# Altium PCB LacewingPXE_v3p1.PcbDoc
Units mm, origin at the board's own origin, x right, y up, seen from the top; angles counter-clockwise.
Board outline 62.74 x 108.59 mm, 2 copper layers (Top Layer, Bottom Layer); 94 components, 74 nets, 455 pads, 79 vias.
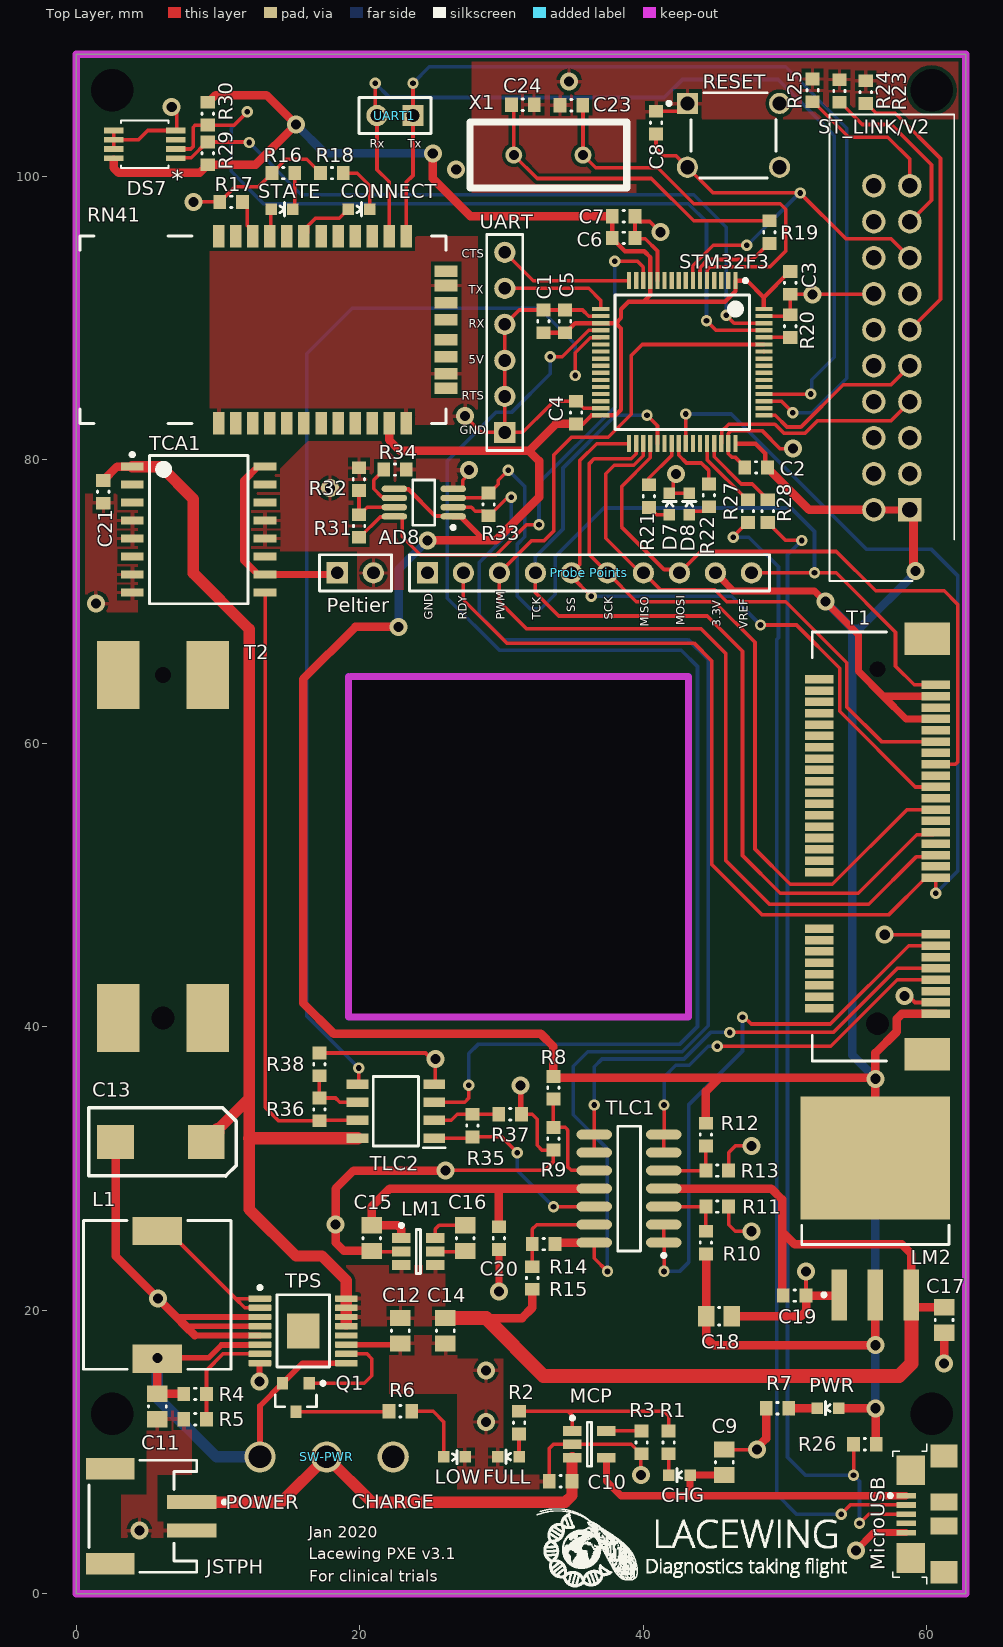
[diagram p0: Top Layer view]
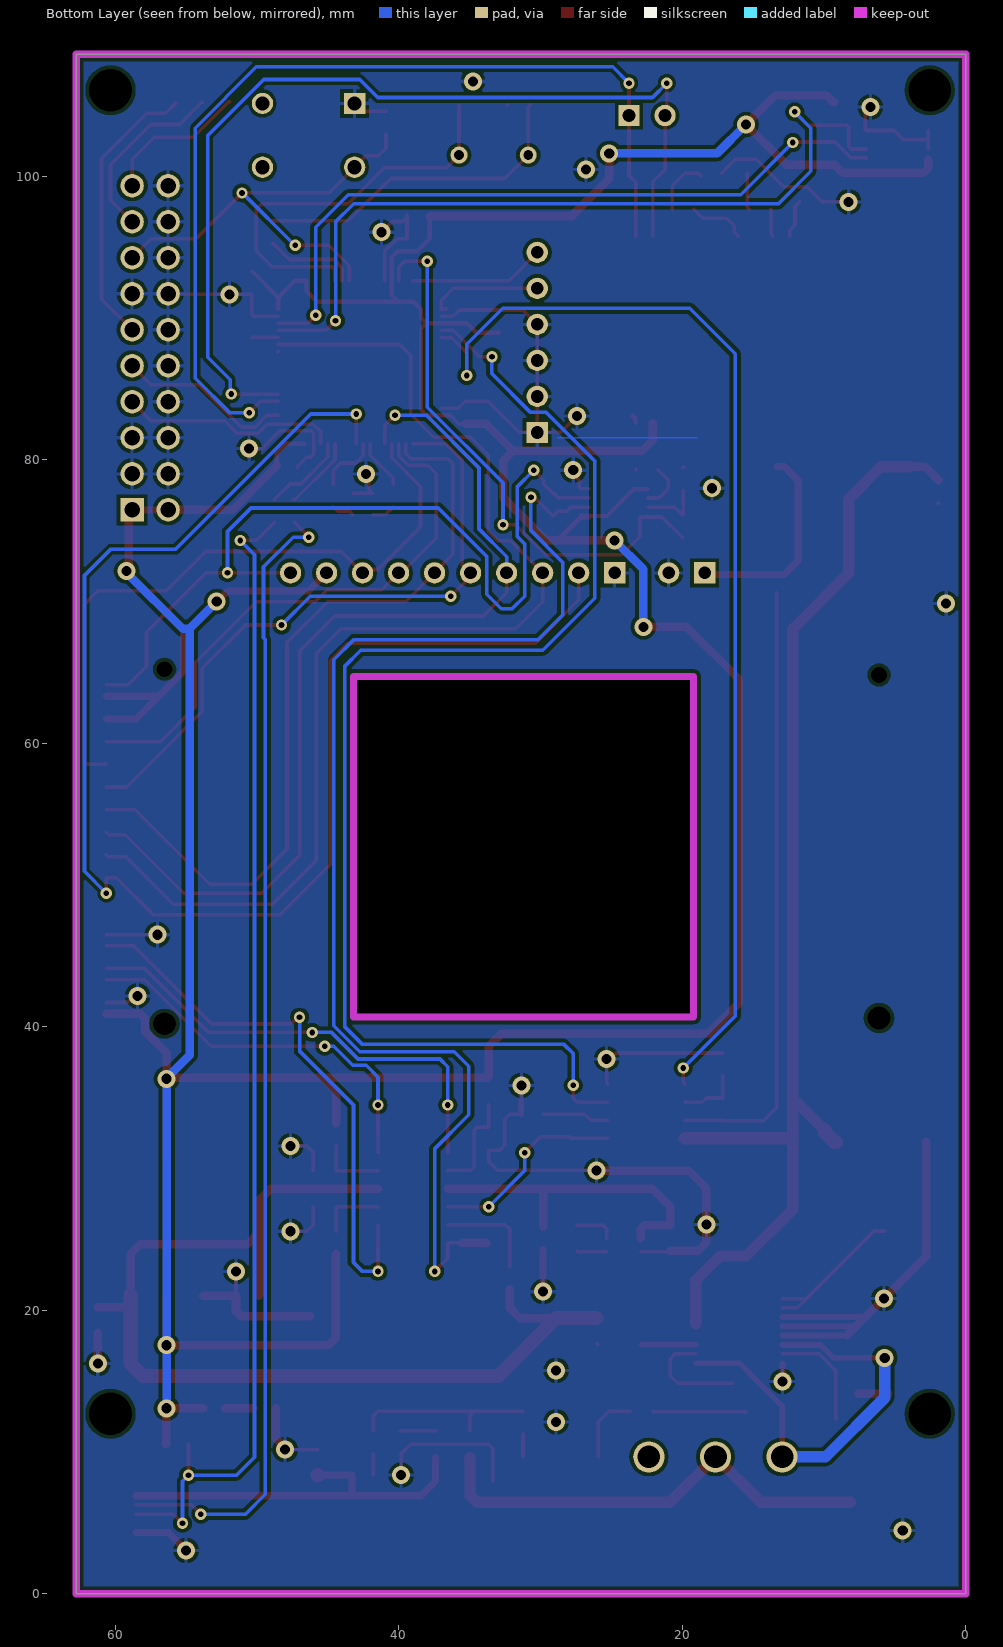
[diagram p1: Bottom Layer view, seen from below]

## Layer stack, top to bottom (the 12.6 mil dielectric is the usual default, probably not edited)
Top Solder: solder mask 0.0102, Solder Resist, Dk 3.5
Top Layer: signal copper 0.0356
Dielectric 1: dielectric 0.32, FR-4, Dk 4.8
Bottom Layer: signal copper 0.0356
Bottom Solder: solder mask 0.0102, Solder Resist, Dk 3.5

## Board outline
0,0 62.738,0 62.738,108.585 0,108.585
cut-out: 43.188,40.672 19.188,40.672 19.188,64.705 43.188,64.705

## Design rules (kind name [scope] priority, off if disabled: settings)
Clearance [All] p1: gap=0.254 ignorepadtopadclearanceinfootprint=TRUE except(0: Arc-Hole Track-Hole SMDPad-Hole THPad-Hole Via-Hole Fill-Hole Poly-Hole Region-Hole Text-Hole; 0.2: Arc-Arc Arc-Track Arc-SMDPad Track-Track Track-SMDPad)
ComponentClearance [All] p1 off: gap=0.254 collisioncheckmode=3 verticalgap=0.254 showdistances=FALSE
HoleSize [All] p1: absolutevalues=TRUE maxlimit=3 minlimit=0.025 maxpercent=80.000 minpercent=20.000
MinimumSolderMaskSliver [All] p1: minsoldermaskwidth=0.1
PolygonConnect [All] p1: connectstyle=Relief reliefconductorwidth=0.254 reliefentries=4 polygonreliefangle="90 Angle" airgapwidth=0.254
RoutingVias [All] p1: holewidth=0.711 width=1.27 viastyle="Through Hole" minholewidth=0.4 minwidth=0.8 maxholewidth=0.711 maxwidth=1.27
SilkToSilkClearance [All] p1: silktosilkclearance=0.1
SilkToSolderMaskClearance [IsPad] p1: minsilkscreentomaskgap=0.1 clearancetoexposedcopper=TRUE
SolderMaskExpansion [All] p1: expansion=0.102 istentingtop=FALSE
Width Width_+5VDD [InNet('+5VDD')] p1: maxlimit=1 minlimit=0.4 preferedwidth=1 minimp=50.000000 maximp=50.000000 favimp=50.000000
Width Width_-5VDD [InNet('-5VDD')] p2: maxlimit=1 minlimit=0.5 preferedwidth=1 minimp=50.000000 maximp=50.000000 favimp=50.000000
Width Width_VLi [InNet('VLiPo')] p3: maxlimit=1 minlimit=0.5 preferedwidth=1 minimp=50.000000 maximp=50.000000 favimp=50.000000
Width Width_VPelt [InNet('Vpeltier')] p4: maxlimit=1 minlimit=0.5 preferedwidth=1 minimp=50.000000 maximp=50.000000 favimp=50.000000
Width Width_5VUSB [InNet('5VUSB')] p5: maxlimit=1 minlimit=0.5 preferedwidth=1 minimp=50.000000 maximp=50.000000 favimp=50.000000
Width Width_VBat [InNet('VBAT')] p6: maxlimit=1 minlimit=0.4 preferedwidth=1 minimp=50.000000 maximp=50.000000 favimp=50.000000
Width Width_3VDD [InNet('3.3VDD')] p7: maxlimit=0.6 minlimit=0.254 preferedwidth=0.6 minimp=50.000000 maximp=50.000000 favimp=50.000000
Width [All] p8: maxlimit=0.6 minlimit=0.254 preferedwidth=0.254 minimp=50.000000 maximp=50.000000 favimp=50.000000
25 further rules are at their usual default settings.

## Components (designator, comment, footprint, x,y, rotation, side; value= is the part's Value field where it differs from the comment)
AD8 "AD8237" ADI-RM-8_N 24.511,76.962 r180 top (schematic designator U3)
C1 "4.7uF" CAPC0603(1608)100_N 32.948,89.751 r90 top
C2 "100nF" CAPC0603(1608)100_N 47.95,79.442 r180 top
C3 "100nF" CAPC0603(1608)100_N 50.363,92.456 r270 top
C4 "100nF" CAPC0603(1608)100_N 35.25,83.312 r90 top
C5 "100nF" CAPC0603(1608)100_N 34.472,89.751 r90 top
C6 "1uF" CAPC0603(1608)100_N 38.608,95.631 r0 top
C7 "10nF" CAPC0603(1608)100_N 38.608,97.163 r0 top
C8 "100nF" CAPC0603(1608)100_N 40.894,103.759 r90 top
C9 "10µF" CAPC0805(2012)75_N 45.72,9.271 r270 top
C10 "4.7µF" CAPC0603(1608)100_N 34.163,7.928 r0 top
C11 "10µF" CAPC0805(2012)75_N 5.715,13.208 r90 top
C12 "2.2µF" CAPC0805(2012)75_N 22.86,18.542 r90 top
C13 "220µF" AVX-CAPC7343_V 5.969,31.877 r180 top
C14 "2.2µF" CAPC0805(2012)75_N 26.035,18.542 r90 top
C15 "10µF" CAPC0805(2012)75_N 20.844,25.08 r270 top
C16 "10µF" CAPC0805(2012)75_N 27.432,25.08 r90 top
C17 "10µF" CAPC0805(2012)75_N 61.214,19.304 r270 top
C18 "10µF" CAPC0805(2012)75_N 45.339,19.569 r180 top
C19 "0.1µF" CAPC0603(1608)100_N 50.673,21.023 r180 top
C20 "0.1µF" CAPC0603(1608)100_N 29.807,25.08 r90 top
C21 "0.1µF" CAPC0603(1608)100_N 1.905,77.724 r90 top
C23 "18pF" CAPC0603(1608)100_N 34.925,104.991 r180 top
C24 "18pF" CAPC0603(1608)100_N 31.496,105.029 r0 top
CHG "Yellow" LED-0603 42.545,8.36 r90 top (schematic designator D1)
CONNECT "Green" LED-0603 19.939,97.663 r270 top (schematic designator D5)
D7 "Red" LED-0603 41.835,76.857 r0 top
D8 "Green" LED-0603 43.229,76.857 r0 top
DS7 "DS7505U+" 21-0036K 4.826,102.235 r180 top value=Value (schematic designator U2)
FULL "Green" LED-0603 30.48,9.652 r90 top (schematic designator D2)
JSTPH "Li-Poly battery" "JST- S2B-PH-SM4-TB(LF)(SN)-2_V" 4.699,5.461 r270 top
L1 "15µH" "WE-PD 1050" 5.715,21.082 r90 top
LM1 "LM2776 Switched-capacitor inverter" TI-DBV6_M 24.13,24.13 r0 top
LM2 "LM1086IS-3.3, 3.3V voltage regulator" TS3B_M 56.368,27.184 r90 top
LOW "Red" LED-0603 26.67,9.652 r270 top (schematic designator D3)
MCP "MCP73831T-2ACI/OT Li-Poly battery charger" SOT-23-OT5_M 36.195,10.541 r0 top
MicroUSB "ZX62R-B-5P" HIRO-ZX62R-B-5P_V 59.876,5.611 r90 top (schematic designator MicroUSB-TypeB)
Peltier "Header 2" HDR1X2 18.415,72.009 r0 top
"Probe Points" "Header 10" HDR1X10 24.765,72.009 r0 top
PWR "Blue" LED-0603 53.017,13.081 r90 top (schematic designator D4)
Q1 "MMUN2133LT1G" ONSC-SOT-23-3-318-08_V 15.494,13.843 r270 top
R1 "1k" RESC0603(1608)_N 41.783,10.668 r90 top
R2 "1k" RESC0603(1608)_N 31.23,12.065 r90 top
R3 "2k" RESC0603(1608)_N 39.878,10.668 r270 top
R4 "2.7M" RESC0603(1608)_N 8.382,14.097 r180 top
R5 "470k" RESC0603(1608)_N 8.382,12.308 r180 top
R6 "1k5" RESC0603(1608)_N 22.86,12.865 r180 top
R7 "200" RESC0603(1608)_N 49.461,13.081 r180 top
R8 "75k" RESC0603(1608)_N 33.655,35.687 r270 top
R9 "24k" RESC0603(1608)_N 33.655,32.093 r270 top
R10 "51k" RESC0603(1608)_N 44.412,24.765 r90 top
R11 "30k" RESC0603(1608)_N 45.212,27.305 r0 top
R12 "51k" RESC0603(1608)_N 44.412,32.385 r270 top
R13 "51k" RESC0603(1608)_N 45.212,29.845 r0 top
R14 "20k" RESC0603(1608)_N 32.965,24.659 r180 top
R15 "20k" RESC0603(1608)_N 32.165,22.269 r270 top
R16 "470" RESC0603(1608)_N 14.605,100.203 r0 top
R17 "10k" RESC0603(1608)_N 10.922,98.171 r0 top
R18 "470" RESC0603(1608)_N 18.034,100.203 r0 top
R19 "0" RESC0603(1608)_N 48.895,96.035 r270 top
R20 "10k" RESC0603(1608)_N 50.363,89.408 r90 top
R21 "510" RESC0603(1608)_N 40.386,77.414 r90 top
R22 "510" RESC0603(1608)_N 44.623,77.474 r90 top
R23 "10k" RESC0603(1608)_N 55.686,105.918 r270 top
R24 "10k" RESC0603(1608)_N 53.828,105.997 r270 top
R25 "10k" RESC0603(1608)_N 51.931,106.046 r270 top
R26 "1.5k" RESC0603(1608)_N 55.626,10.541 r0 top
R27 "22" RESC0603(1608)_N 47.371,76.365 r90 top
R28 "22" RESC0603(1608)_N 48.768,76.365 r90 top
R29 "10k" RESC0603(1608)_N 9.271,101.6 r270 top
R30 "10k" RESC0603(1608)_N 9.271,104.394 r90 top
R31 "1M" RESC0603(1608)_N 19.95,75.311 r270 top
R32 "1k" RESC0603(1608)_N 19.939,78.613 r270 top
R33 "10k" RESC0603(1608)_N 29.083,76.835 r270 top
R34 "1k" RESC0603(1608)_N 22.479,79.294 r180 top
R35 "10k" RESC0603(1608)_N 27.94,33.02 r270 top
R36 "10k" RESC0603(1608)_N 17.145,34.163 r270 top
R37 "20k" RESC0603(1608)_N 30.607,33.82 r180 top
R38 "20k" RESC0603(1608)_N 17.145,37.338 r270 top
RESET "Tactile switch" OMRON-B3F-1000-4_V 46.355,102.87 r0 top (schematic designator SW-RST1)
RN41 "Bluetooth module w/ antenna" RN41 18.071,89.154 r0 top (schematic designator RN)
ST_LINK/V2 "JTAG Programmer" JTAG2 58.801,76.454 r90 top (schematic designator CN1)
STATE "Red" LED-0603 14.517,97.663 r270 top (schematic designator D6)
STM32F3 "STM32F303RET6" STM-LQFP64_V 42.743,86.868 r270 top (schematic designator U1)
SW-PWR "SW-SPDT" "SWITCH SPDT CS12ANW03" 17.653,9.652 r90 top
T1 "Mini PCIe connector" "Molex Conn-67910" 56.515,52.705 r90 top
T2 "Mini PCIe Latch" "Molex Latch-48099" 6.115,52.705 r90 top
TCA1 "TCA0372 Dual high power Op-amp" ONSC-SOIC-16-751G-03_V 8.636,75.057 r0 top
TLC1 "TLC2274 Quad Op-amp" TI-D14_M 38.989,28.575 r180 top
TLC2 "TLC2272AID" SOIC127P600X175-8N 22.543,34.036 r180 top
TPS "TPS61032 Boost SMPS controller" PW0016A_M 16.002,18.542 r0 top
UART "Header 6" HDR1X6 30.226,81.915 r90 top (schematic designator UART2)
UART1 "Header 2" HDR1X2 23.749,104.267 r180 top
X1 "8MHz" QCL 33.301,101.473 r180 top

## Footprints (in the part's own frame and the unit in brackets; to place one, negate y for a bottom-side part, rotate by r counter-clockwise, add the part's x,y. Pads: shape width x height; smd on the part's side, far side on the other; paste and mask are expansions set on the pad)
21-0036K [mil]
  rect 54x16 smd paste+0 mask+0: 1(-86,38.39) 2(-86,12.8) 3(-86,-12.8) 4(-86,-38.39) 5(86,-38.39) 6(86,-12.8) 7(86,12.8) 8(86,38.39)
  silkscreen extent -66,-66 66,66, body extent 0,0 10,10, height 10
ADI-RM-8_N [mm] "SOP, 8-Leads, Body 3x3mm, Pitch 0.65mm, IPC Medium Density"
  oval 1.8x0.45 smd: 1(-2.075,0.975) 2(-2.075,0.325) 3(-2.075,-0.325) 4(-2.075,-0.975) 5(2.075,-0.975) 6(2.075,-0.325) 7(2.075,0.325) 8(2.075,0.975)
  silkscreen extent -2.2,-1.6 0.77,1.87, body extent -1.6,-1.6 1.6,1.6, height 1.1
AVX-CAPC7343_V [mm] "SMT Capacitor, 2 Leads, Body 7.3x4.3mm"
  rect 2.6x2.4 smd: 1(-3.202,0.007) 2(3.198,0.007)
  silkscreen extent -5.33,-2.39 5.08,2.41, body extent -3.49,-2.03 3.51,2.04, height 4.05
CAPC0603(1608)100_N [mm] "Chip Capacitor, Body 1.6x0.8mm, Height 1.0mm, IPC Medium Density"
  rect 0.9x1 smd: 1(-0.8,0) 2(0.8,0)
  silkscreen extent -0.05,-0.4 0.05,0.4, body extent -0.87,-0.48 0.88,0.47, height 1
CAPC0805(2012)75_N [mm] "Chip Capacitor, Body 2.0x1.2mm, Height 0.75mm, IPC Medium Density"
  rect 1.15x1.45 smd: 1(-0.9,0) 2(0.9,0)
  silkscreen extent -0.05,-0.62 0.05,0.63, body extent -1.1,-0.72 1.1,0.73, height 0.75
HDR1X2 [mm] "Connector; Header; 2 Position"
  rect 1.5x1.5 hole 0.9: 1(0,0)
  round 1.5 hole 0.9: 2(2.54,0)
  silkscreen extent -1.27,-1.27 3.81,1.27
HDR1X6 [mm] "Connector; Header; 6 Position"
  rect 1.5x1.5 hole 0.9: 1(0,0)
  round 1.5 hole 0.9: 2(2.54,0) 3(5.08,0) 4(7.62,0) 5(10.16,0) 6(12.7,0)
  silkscreen extent -1.27,-1.27 13.97,1.27
HDR1X10 [mm] "Connector; Header; 10 Position"
  rect 1.5x1.5 hole 0.9: 1(0,0)
  round 1.5 hole 0.9: 2(2.54,0) 3(5.08,0) 4(7.62,0) 5(10.16,0) 6(12.7,0) 7(15.24,0) 8(17.78,0) 9(20.32,0) 10(22.86,0)
  silkscreen extent -1.27,-1.27 24.13,1.27
HIRO-ZX62R-B-5P_V [mm] "USB Micro-B R/A Connector"
  rect 0.4x1.35 smd: 1(1.3,1.338) 2(0.65,1.338) 3(0,1.338) 4(-0.65,1.338) 5(-1.3,1.338)
  rect 2.1x2 smd: 6(-3.1,1.012) 11(3.1,1.012)
  rect 1.6x1.9 smd: 7(-4.1,-1.338) 10(4.1,-1.338)
  rect 1.2x1.9 smd: 8(-0.85,-1.338) 9(0.85,-1.338)
  silkscreen extent -4.95,-0.13 4.95,2.58, body extent -4.4,-3.95 4.4,1.78, height 2.71
"JST- S2B-PH-SM4-TB(LF)(SN)-2_V" [mm] "SMD, 2-Leads, Body 7.9x7.6mm, Pitch 2mm"
  rect 1x3.5 smd: 1(-1,3.45) 2(1,3.45)
  rect 1.5x3.4 smd: MP1(-3.35,-2.3) MP2(3.35,-2.3)
  silkscreen extent -3.95,-3.8 3.95,5.88, body extent -3.95,-3.8 3.95,4.8, height 5.6
JTAG2 [mm] "Header, Vertical Shrouded, 100 mil pitch; 25 mil lead width, 20 pins, 2 rows, 10 pins per row, 1295 mil L X 346 mil W X 346 mil H body"
  rect 1.652x1.652 hole 1.101 paste-1.652: 1(0,0)
  round 1.652 hole 1.101 paste-1.652: 2(0,2.54) 3(2.54,0) 4(2.54,2.54) 5(5.08,0) 6(5.08,2.54) 7(7.62,0) 8(7.62,2.54) 9(10.16,0) 10(10.16,2.54) 11(12.7,0) 12(12.7,2.54) 13(15.24,0) 14(15.24,2.54) 15(17.78,0) 16(17.78,2.54) 17(20.32,0) 18(20.32,2.54) 19(22.86,0) 20(22.86,2.54)
  silkscreen extent -5.02,-3.12 27.88,5.66, body extent -3.18,-3.56 26.04,5.92, height 8.89
LED-0603 [mil] "LED-0603"
  rect 32x32 smd: A(0,-29.53) C(0,30)
  silkscreen extent -18,-6 19,7
"Molex Conn-67910" [mm] "Board-to-Board Connector, SMT, Right Angle, Pitch 0.8mm, 52-Position, Female"
  rect 0.6x2 smd: 1(-11.8,-4.1) 2(-11.4,4.1) 3(-11,-4.1) 4(-10.6,4.1) 5(-10.2,-4.1) 6(-9.8,4.1) 7(-9.4,-4.1) 8(-9,4.1) 9(-8.6,-4.1) 10(-8.2,4.1) 11(-7.8,-4.1) 12(-7.4,4.1) 13(-7,-4.1) 14(-6.6,4.1) 15(-6.2,-4.1) 16(-5.8,4.1) 17(-2.2,-4.1) 18(-1.8,4.1) 19(-1.4,-4.1) 20(-1,4.1) 21(-0.6,-4.1) 22(-0.2,4.1) 23(0.2,-4.1) 24(0.6,4.1) 25(1,-4.1) 26(1.4,4.1) 27(1.8,-4.1) 28(2.2,4.1) 29(2.6,-4.1) 30(3,4.1) 31(3.4,-4.1) 32(3.8,4.1) 33(4.2,-4.1) 34(4.6,4.1) 35(5,-4.1) 36(5.4,4.1) 37(5.8,-4.1) 38(6.2,4.1) 39(6.6,-4.1) 40(7,4.1) 41(7.4,-4.1) 42(7.8,4.1) 43(8.2,-4.1) 44(8.6,4.1) 45(9,-4.1) 46(9.4,4.1) 47(9.8,-4.1) 48(10.2,4.1) 49(10.6,-4.1) 50(11,4.1) 51(11.4,-4.1) 52(11.8,4.1)
  round 1.3 hole 1.6 unplated: MH1(-12.5,0)
  round 0.8 hole 1.1 unplated: MH2(12.5,0)
  rect 2.3x3.2 smd: MP1C(-14.65,-3.5) MP2C(14.65,-3.5)
  silkscreen extent -15.12,-0.64 15.12,4.6, body extent -15,-5 15,4.5, height 5.6
"Molex Latch-48099" [mm]
  round 1.3 hole 1.6 unplated: MH3(-12.1,0)
  round 0.8 hole 1.1 unplated: MH4(12.1,0)
  rect 4.8x3 smd: MP1L(-12.1,3.15) MP2L(-12.1,-3.15) MP3L(12.1,3.15) MP4L(12.1,-3.15)
OMRON-B3F-1000-4_V [mm] "TH, 4-Leads, Body 6x6mm"
  rect 1.5x1.5 hole 1 paste+0: 1(-3.25,2.25)
  round 1.5 hole 1 paste+0: 2(3.25,2.25) 3(-3.25,-2.25) 4(3.25,-2.25)
  silkscreen extent -4.67,-3 3,3, body extent -3,-3 3,3, height 4.5
ONSC-SOIC-16-751G-03_V [mm] "SOIC, 16-Leads, Body 10.45x7.6mm, Pitch 1.27mm"
  rect 1.62x0.58 smd: 1(-4.69,4.445) 2(-4.69,3.175) 3(-4.69,1.905) 4(-4.69,0.635) 5(-4.69,-0.635) 6(-4.69,-1.905) 7(-4.69,-3.175) 8(-4.69,-4.445) 9(4.69,-4.445) 10(4.69,-3.175) 11(4.69,-1.905) 12(4.69,-0.635) 13(4.69,0.635) 14(4.69,1.905) 15(4.69,3.175) 16(4.69,4.445)
  silkscreen extent -4.81,-5.23 3.48,5.41, body extent -3.8,-5.23 3.8,5.23, height 2.65
ONSC-SOT-23-3-318-08_V [mm] "SOT23, 3-Leads, Body 2.92x1.3mm, Pitch 0.95mm"
  rect 0.9x0.8 smd: 1(-1,0.95) 2(-1,-0.95) 3(1,0)
  silkscreen extent -1.12,-1.46 0.65,2.03, body extent -0.65,-1.46 0.65,1.46, height 1.11
PW0016A_M [mm] "SOP, 16-Leads, Body 5.1x4.5mm, Pitch 0.65mm, IPC Low Density"
  rrect22% 1.6x0.45 smd: 1(-3.05,2.275) 2(-3.05,1.625) 3(-3.05,0.975) 4(-3.05,0.325) 5(-3.05,-0.325) 6(-3.05,-0.975) 7(-3.05,-1.625) 8(-3.05,-2.275) 9(3.05,-2.275) 10(3.05,-1.625) 11(3.05,-0.975) 12(3.05,-0.325) 13(3.05,0.325) 14(3.05,0.975) 15(3.05,1.625) 16(3.05,2.275)
  rect 2.31x2.46 smd: PowerPAD(0,0)
  silkscreen extent -3.17,-2.55 1.85,3.17, body extent -3.21,-2.5 3.21,2.5, height 1
QCL [mm]
  round 1.2 hole 0.7: 1(-2.44,0) 2(2.44,0)
  silkscreen extent -5.53,-2.32 5.53,2.32
RESC0603(1608)_N [mm] "Chip Resistor, Body 1.6x0.8mm, IPC Medium Density"
  rect 0.9x1 smd: 1(-0.8,0) 2(0.8,0)
  silkscreen extent -0.05,-0.4 0.05,0.4, body extent -0.85,-0.47 0.85,0.47, height 0.6
RN41 [mil]
  rect 32x63 smd: 1(-315.42,-259.92) 2(-268.18,-259.92) 3(-220.93,-259.92) 4(-173.69,-259.92) 5(-126.44,-259.92) 6(-79.2,-259.92) 7(-31.58,-259.92) 8(15.42,-259.92) 9(63.42,-259.92) 10(110.42,-259.92) 11(157.42,-259.92) 12(204.42,-259.92) 13(204.42,259.92) 14(157.42,259.92) 15(110.42,259.92) 16(63.42,259.92) 17(15.42,259.92) 18(-31.58,259.92) 19(-79.2,259.92) 20(-126.44,259.92) 21(-173.69,259.92) 22(-220.93,259.92) 23(-268.18,259.92) 24(-315.42,259.92)
  rect 63x32 smd: 28(315.42,122.92) 29(315.42,-122.13) 30(315.42,162.92) 31(315.42,74.92) 32(315.42,27.92) 33(315.42,-27.64) 34(315.42,-74.88) 35(315.42,-162.37)
  silkscreen extent -701,-260 315,260
SOIC127P600X175-8N [mm]
  rect 1.525x0.65 smd: 1(-2.712,1.905) 2(-2.712,0.635) 3(-2.712,-0.635) 4(-2.712,-1.905) 5(2.712,-1.905) 6(2.712,-0.635) 7(2.712,0.635) 8(2.712,1.905)
  silkscreen extent -3.47,-2.45 1.6,2.58, body extent -3,-2.45 3,2.45, height 1.75
SOT-23-OT5_M [mm] "SOT23, 5-Leads, Body 2.9x1.7mm, Pitch 0.95mm, Lead Span 2.8mm, IPC Low Density"
  rect 1.3x0.7 smd: 1(-1.2,0.95) 2(-1.2,0) 3(-1.2,-0.95) 4(1.2,-0.95) 5(1.2,0.95)
  silkscreen extent -1.32,-1.55 0.15,1.97, body extent -0.9,-1.55 0.9,1.55, height 1.45
STM-LQFP64_V [mm] "Thin QFP, 64-Leads, Body 10x10mm, Pitch 0.5mm, ST Recommended"
  rect 1.2x0.3 smd: 1(-5.75,3.75) 2(-5.75,3.25) 3(-5.75,2.75) 4(-5.75,2.25) 5(-5.75,1.75) 6(-5.75,1.25) 7(-5.75,0.75) 8(-5.75,0.25) 9(-5.75,-0.25) 10(-5.75,-0.75) 11(-5.75,-1.25) 12(-5.75,-1.75) 13(-5.75,-2.25) 14(-5.75,-2.75) 15(-5.75,-3.25) 16(-5.75,-3.75) 33(5.75,-3.75) 34(5.75,-3.25) 35(5.75,-2.75) 36(5.75,-2.25) 37(5.75,-1.75) 38(5.75,-1.25) 39(5.75,-0.75) 40(5.75,-0.25) 41(5.75,0.25) 42(5.75,0.75) 43(5.75,1.25) 44(5.75,1.75) 45(5.75,2.25) 46(5.75,2.75) 47(5.75,3.25) 48(5.75,3.75)
  rect 0.3x1.2 smd: 17(-3.75,-5.75) 18(-3.25,-5.75) 19(-2.75,-5.75) 20(-2.25,-5.75) 21(-1.75,-5.75) 22(-1.25,-5.75) 23(-0.75,-5.75) 24(-0.25,-5.75) 25(0.25,-5.75) 26(0.75,-5.75) 27(1.25,-5.75) 28(1.75,-5.75) 29(2.25,-5.75) 30(2.75,-5.75) 31(3.25,-5.75) 32(3.75,-5.75) 49(3.75,5.75) 50(3.25,5.75) 51(2.75,5.75) 52(2.25,5.75) 53(1.75,5.75) 54(1.25,5.75) 55(0.75,5.75) 56(0.25,5.75) 57(-0.25,5.75) 58(-0.75,5.75) 59(-1.25,5.75) 60(-1.75,5.75) 61(-2.25,5.75) 62(-2.75,5.75) 63(-3.25,5.75) 64(-3.75,5.75)
  silkscreen extent -5.87,-4.75 4.75,4.75, body extent -5,-5 5,5, height 1.6
"SWITCH SPDT CS12ANW03" [mm]
  round 2.2 hole 1.6: 1(0,-4.7) 2(0,0) 3(0,4.7)
TI-D14_M [mm] "SOIC, 14-Leads, Body 8.65x3.9mm, Pitch 1.27mm, IPC Low Density"
  oval 2.5x0.7 smd: 1(-2.45,3.81) 2(-2.45,2.54) 3(-2.45,1.27) 4(-2.45,0) 5(-2.45,-1.27) 6(-2.45,-2.54) 7(-2.45,-3.81) 8(2.45,-3.81) 9(2.45,-2.54) 10(2.45,-1.27) 11(2.45,0) 12(2.45,1.27) 13(2.45,2.54) 14(2.45,3.81)
  silkscreen extent -2.58,-4.4 0.8,4.83, body extent -2,-4.38 2,4.38, height 1.75
TI-DBV6_M [mm] "SOT-23, 6-Leads, Body 2.90x1.60mm, Pitch 0.95mm, IPC Low Density"
  rect 1.3x0.7 smd: 1(-1.2,0.95) 2(-1.2,0) 3(-1.2,-0.95) 4(1.2,-0.95) 5(1.2,0) 6(1.2,0.95)
  silkscreen extent -1.32,-1.55 0.15,1.97, body extent -0.87,-1.52 0.87,1.53, height 1.45
TS3B_M [mm] "D2-PAK, 4-Leads, Body 8.6x10.2mm, Pitch 2.54mm, Lead Span 14.2mm, IPC Low Density"
  rect 3.6x1.1 smd: 1(-6.1,2.54) 2(-6.1,0) 3(-6.1,-2.54)
  rect 8.7x10.55 smd: TAB(3.55,0)
  silkscreen extent -6.22,-5.2 -1.2,5.2, body extent -2.55,-5.2 6.34,5.2, height 4.64
"WE-PD 1050" [mm] "SMD Inductor, 2-Leads, Body 10,0x10,0mm"
  rect 2x3.5 smd: 1(-4.5,0) 2(4.5,0)
  silkscreen extent -5.25,-5.2 5.25,5.2, body extent -5,-5 5,5, height 4.75

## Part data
C1 C2 C3 C4 C5 C6 C7 C8 C23 C24: library part CMP-1035-00032-1, "Ceramic CAP0603 (1608 Metric) Thickness 1mm SMD", Case-EIA=0603
C9 C11 C12 C14 C15 C16 C17 C18: library part CMP-1036-00002-1, "Ceramic CAP0805 (2012 Metric) Thickness 0.75mm SMD", Case-EIA=0805, Rated Voltage="10 V"
C10: library part CMP-1035-00032-1, "Ceramic CAP0603 (1608 Metric) Thickness 1mm SMD", Case-EIA=0603, Rated Voltage="10 V"
C13: library part CMP-0279-00002-1, "Capacitor, Tantalum, 220uF 10% 10V MCCT-D (7343-31)", Manufacturer=AVX, PartNumber=TAJD227K010R, Rated Voltage=10V, Tolerance=10%
C19 C20 C21: library part CAP, "Ceramic CAP0603 (1608 Metric) Thickness 1mm SMD", Case-EIA=0603
CHG CONNECT D7 D8 FULL LOW PWR STATE: library part LED0603, "LED SMD 0603"
DS7: library part ds7505u+, "No Description Available"
JSTPH: library part CN-1P-2M-R2, "JST PH 2-pin 2-holder SMD"
L1: library part CMP-1396-00032-1, "SMD-Shielded Power Inductor WE-PD 7447714150, L=15 µH"
LM1: library part LM2776
LM2: library part LM1086IS-3.3
MCP: library part CMP-0133-00143-1, "Miniature Single-Cell, Fully Integrated Li-Ion, Li-Polymer Charge Management Controller, 4.2V, 5-Pin SOT-23, Industrial Temperature, Tape and Reel"
MicroUSB: library part CMP-0031-00001-1, "Connector; USBMicro-B,Reverse type, SMT; 5 Position; Right Angle", Operating Temperature="-30 to 85 degC"
Peltier UART1: "Header, 2-Pin"
"Probe Points": "Header, 10-Pin"
Q1: library part CMP-0630-00284-1, "Digital Transistor (BRT), R1=4.7 kOhm, R2=47 kOhm, PNP Transistor, 3-Pin SOT-23, Pb-Free, Tape and Reel"
R1 R2 R3 R4 R5 R6 R7 R8 R9 R10 R11 R12 R13 R14 R15 R16 R17 R18 R19 R20 R21 R22 R23 R24 R25 R26 R27 R28 R29 R30 R31 R32 R33 R34 R35 R36 R37 R38: library part CMP-1012-00514-1, "RES0603 (1608 Metric)  SMD", Case-EIA=0603
RESET: library part SW-SPST-4_A, "ORMON B3F-10XX"
RN41: library part BLUETOOTH-RN41, "Bluetooth SMD module"
ST_LINK/V2: library part JTAG
STM32F3: library part STM32F303RBT6_1, "ARM Cortex-M4 32-bit MCU, 128 KB Flash, 32 KB Internal RAM, 52 I/Os, 64-pin LQFP, -40 to 85 degC, Tray", I/Os (High Current)=52, Operating Frequency(F) (Processor speed) (MHz)=72, PartNumber=STM32F303RBT6, Supplier Part Number 1=STM32F303RBT6-ND, Supply Voltage(Vcc) min (V)=2
SW-PWR: "Switch SPDT CS12ANW03"
TCA1: library part TCA0372
TLC1: library part TLC2274
TLC2: "Integrated Circuit", Manufacturer_Name="Texas Instruments", Mouser Part Number=595-TLC2272AID, RS Part Number=4621437P
TPS: library part TPS61032
UART: "Header, 6-Pin"
X1: library part XTAL, "Crystal Oscillator"

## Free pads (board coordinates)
  round 1.524 hole 3 unplated: MH3(2.54,12.7) MH3(2.54,106.045) MH3(60.325,12.7) MH3(60.325,106.045)

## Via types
v1: diameter 1.27, hole 0.711, Top Layer to Bottom Layer, 41 vias
v2: diameter 0.8, hole 0.4, Top Layer to Bottom Layer, 38 vias

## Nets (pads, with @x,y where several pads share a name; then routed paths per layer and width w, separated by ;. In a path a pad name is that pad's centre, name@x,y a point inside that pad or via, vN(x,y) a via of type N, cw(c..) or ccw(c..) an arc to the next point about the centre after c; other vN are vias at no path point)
3.3VDD: "Probe Points.9" AD8.1 AD8.5 C1.1 C2.1 C3.1 C4.1 C5.1 C6.1 C7.1 C18.2 DS7.8 LM2.2 LM2.TAB PWR.A R8.1 R10.1 R12.1 R26.2 R29.2 R30.2 RN41.11 ST_LINK/V2.1 ST_LINK/V2.2 STM32F3.1 STM32F3.13 STM32F3.19 STM32F3.32 STM32F3.48 STM32F3.64 T1.1 T1.45 T1.49 | length 358.3
  Top Layer w0.254: AD8.5 AD8.5@22.474,77.899 ; AD8.1@26.548,76.025 AD8.1 ; C6.1@37.808,95.581 C6.1 ; STM32F3.13 40.488,92.623 STM32F3.13@40.493,92.628 ; C3.1@50.313,93.256 C3.1
  Top Layer w0.3: AD8.5@22.474,77.899 23.437,77.899 25.312,76.025 AD8.1@26.548,76.025 ; C1.1 C5.1 ; C5.1@34.522,88.951 35.189,89.618 STM32F3.19 38.047,89.618 ; C4.1 35.733,82.512 36.339,83.118 STM32F3.32 ; STM32F3.32@37.211,83.118 38.033,83.118 38.425,83.51 38.425,89.24 38.047,89.618 ; C6.1@37.808,95.581 38.701,94.688 40.067,94.688 40.493,94.262 STM32F3.13@40.493,92.628 ; C6.1 C7.1 ; STM32F3.13 40.493,91.618 40.005,91.13 ; 46.643,81.118 47.903,81.118 48.6,80.421 C2.1@48.6,79.592 ; STM32F3.64@48.493,90.626 48.493,91.436 ; C3.1@50.313,93.256 48.493,91.436 ; 38.047,89.618 38.425,89.996 38.425,90.604 38.951,91.13 40.005,91.13 ; 40.005,91.13 45.75,91.13 46.493,91.873 STM32F3.1 47.311,92.618 48.493,91.436
  Top Layer w0.4: AD8.1 27.111,75.987 28.806,74.292
  Top Layer w0.5: 45.329,72.009 45.329,71.765 46.355,70.739 52.07,70.739 v1(52.832,69.977) 55.187,67.622 55.187,65.042 56.924,63.305 ; ST_LINK/V2.2 ST_LINK/V2.1 ; T1.45 58.524,61.705 56.924,63.305 ; T1.49 56.924,63.305
  Top Layer w0.6: DS7.8@2.636,101.163 2.636,100.571 2.987,100.219 8.69,100.219 R29.2 ; R29.2@9.221,100.8 R29.2 ; R30.2 9.321,105.194 9.471,105.344 9.471,105.359 9.822,105.71 13.416,105.71 v1(15.494,103.632) 12.662,100.8 R29.2 ; RN41.11 22.069,81.386 22.845,80.611 31.929,80.611 ; v1(22.733,68.199) 19.685,68.199 16.002,64.516 16.002,41.656 18.161,39.497 32.766,39.497 33.655,38.608 R8.1 33.731,36.411 45.399,36.411 ; v1(24.765,74.292) 28.806,74.292 29.588,74.292 32.639,77.343 32.639,79.901 31.929,80.611 ; v1(25.146,101.6) 25.146,99.822 27.805,97.163 C7.1 ; C4.1 33.83,82.512 31.929,80.611 ; R10.1 44.425,23.952 44.425,19.583 C18.2 44.439,18.045 44.958,17.526 v1(56.368,17.526) LM2.2 ; R12.1 44.412,35.424 45.399,36.411 ; 45.085,72.009 45.329,72.009 ; C2.1@48.6,79.592 C2.1 48.75,79.392 51.688,76.454 ST_LINK/V2.2 ; PWR.A v1(56.368,13.081) 56.397,13.052 56.397,10.57 R26.2 ; LM2.TAB v1(56.368,36.322) 56.279,36.411 45.399,36.411 ; v1@56.368,36.342 56.368,38.143 57.869,39.644 57.869,40.539 58.235,40.905 T1.1 ; ST_LINK/V2.1 59.054,76.201 59.054,72.264 v1(59.182,72.136)
  Bottom Layer w0.6: v1(15.494,103.632) 17.526,101.6 v1(25.146,101.6) ; v1(22.733,68.199) 22.733,72.26 v1(24.765,74.292) ; v1(52.832,69.977) 54.737,68.072 ; v1(56.368,13.081) v1(56.368,17.526) v1(56.368,36.322) 56.368,36.363 54.737,37.994 54.737,68.072 ; v1(59.182,72.136) 59.182,72.009 55.245,68.072 54.737,68.072
5VUSB: C9.2 CHG.A MCP.4 MicroUSB.1 | length 27.1
  Top Layer w0.5: MCP.4 37.395,7.928 38.412,6.911 43.295,6.911 ; C9.2@45.709,8.36 CHG.A 43.295,6.911 ; MicroUSB.1 43.295,6.911
  Top Layer w1: C9.2@45.709,8.36 C9.2
+5VDD: C12.2 C13.1 C14.2 C17.1 C19.2 C21.2 LM1.3 LM1.4 LM2.3 R15.2 TCA1.1 TLC1.4 TLC2.8 TPS.13 TPS.14 TPS.15 TPS.16 | length 158.4
  Top Layer w0.5: TLC2.8@19.807,32.106 TLC2.8
  Top Layer w0.6: C21.2 2.883,79.502 TCA1.1 ; 28.89,19.442 31.44,19.442 32.165,20.167 R15.2 ; TLC1.4 49.022,28.575 49.784,27.813 49.784,21.112 C19.2 ; 49.873,25.438 50.673,24.638 58.235,24.638 58.908,23.965 LM2.3 ; LM2.3@58.958,20.204 C17.1
  Top Layer w0.8: TCA1.1 5.969,79.502 8.255,77.216 8.255,71.986 12.192,68.049 12.192,34.925 ; C13.1@9.971,32.704 12.192,34.925 ; TPS.13@19.05,19.05 19.05,22.098 17.332,23.816 15.494,23.816 12.192,27.118 12.192,32.131 12.192,34.925
  Top Layer w0.89: 12.192,32.131 TLC2.8
  Top Layer w1: C13.1 9.271,31.87 9.971,32.57 C13.1@9.971,32.704 ; C14.2 28.89,19.442 32.965,15.367 58.039,15.367 58.908,16.236 LM2.3@58.908,20.254 ; LM2.3 LM2.3@58.908,20.254 ; LM2.3@58.958,20.204 LM2.3@58.908,20.254
-5VDD: C15.1 C20.2 LM1.1 TLC1.11 | length 23.1
  Top Layer w0.6: LM1.1 22.93,25.721 22.671,25.98 C15.1 20.844,27.305 22.114,28.575 29.807,28.575 ; C20.2 29.807,28.575 ; TLC1.11 29.807,28.575
GND: "Probe Points.1" AD8.4 C1.2 C2.2 C3.2 C4.2 C5.2 C6.2 C7.2 C8.2 C9.1 C10.1 C11.1 C12.1 C13.2 C14.1 C15.2 C17.2 C18.1 C19.1 C20.1 C21.1 C23.2 C24.2 D7.C D8.C DS7.4 DS7.5 DS7.6 DS7.7 FULL.C JSTPH.2 LM1.2 LM2.1 LOW.C MCP.2 MicroUSB.5 Peltier.2 R3.2 R5.2 R7.2 R9.2 R11.2 R13.2 R16.1 R17.1 R18.1 R20.2 R23.1 R24.1 R25.1 R32.1 R34.1 R37.1 R38.1 RESET.1 RN41.1 RN41.12 RN41.28 RN41.29 ST_LINK/V2.3 ST_LINK/V2.4 ST_LINK/V2.5 ST_LINK/V2.6 ST_LINK/V2.8 ST_LINK/V2.10 ST_LINK/V2.12 ST_LINK/V2.13 ST_LINK/V2.14 ST_LINK/V2.16 ST_LINK/V2.18 ST_LINK/V2.20 STM32F3.12 STM32F3.18 STM32F3.31 STM32F3.47 STM32F3.63 T1.3 T1.15 TCA1.4 TCA1.5 TCA1.7 TCA1.8 TCA1.12 TCA1.13 TLC2.4 TPS.3 TPS.4 TPS.5 TPS.8 TPS.11 UART.1 UART.2 UART.3 UART.4 | length 206.5
  Top Layer w0.254: C21.1 C21.1@1.955,76.924 ; DS7.7 2.639,101.913 2.639,102.557 DS7.6 ; DS7.5 2.639,103.207 2.639,102.563 DS7.6 ; v1(6.731,104.864) 7.087,104.508 7.087,103.286 DS7.4 5.039,103.21 4.389,102.56 DS7.6 ; v1(8.255,98.171) R17.1 11.179,99.228 12.83,99.228 R16.1 14.779,101.177 16.26,101.177 R18.1 ; TPS.8@12.927,16.242 TPS.8 ; R38.1 24.636,38.138 25.055,37.719 v1(25.33,37.719) 25.33,36.016 TLC2.4 ; R32.1@19.85,79.502 R32.1 R32.1@19.989,79.413 ; Peltier.2@20.592,72.009 Peltier.2 ; C15.2 20.894,24.13 LM1.2 ; C12.1@22.86,17.567 C12.1 ; RN41.12 23.263,82.779 RN41.12@23.542,83.058 ; RN41.12@23.263,82.946 RN41.12@23.459,83.142 ; R34.1 R34.1@23.279,79.344 ; C14.1@25.96,17.567 C14.1 ; v1(26.035,29.845) 26.049,29.859 33.034,29.859 33.655,30.48 R9.2 32.842,31.293 32.512,31.623 32.512,33.473 32.165,33.82 R37.1 R37.1@31.344,33.82 ; AD8.4 27.165,77.937 27.256,78.028 27.256,78.543 27.686,78.973 v1(27.686,79.248) ; v1(27.432,83.058) 28.575,81.915 UART.1 ; C24.2 C24.2@32.334,104.991 ; C10.1 33.363,10.249 33.655,10.541 MCP.2 39.155,10.541 39.828,9.868 v1(39.828,8.36) ; STM32F3.31 35.794,83.618 35.3,84.112 C4.2 33.693,84.112 33.274,83.693 31.496,81.915 UART.1 ; STM32F3.18 36.14,90.118 35.707,90.551 C5.2 C1.2 31.242,90.551 UART.4 UART.3 UART.2 UART.1 ; C7.2@39.408,97.213 C7.2 C7.2@39.408,97.113 ; C8.2 42.544,104.559 RESET.1 ; STM32F3.12 40.993,94.711 40.123,95.581 39.408,95.581 C6.2 C7.2@39.408,97.113 ; v1(41.202,96.035) 40.447,96.79 39.731,96.79 C7.2@39.408,97.113 ; v1(42.307,78.994) 42.114,78.802 42.114,77.898 D7.C 43.228,77.619 D8.C ; C9.1 45.731,10.16 v1(48.006,10.16) v1@48.006,10.286 ; R11.2 46.012,26.035 46.482,25.565 v1(47.625,25.565) ; R13.2 46.012,31.115 46.482,31.585 v1(47.625,31.585) ; C2.2 47.15,79.492 46.468,80.174 46.225,80.174 45.993,80.406 STM32F3.47 45.993,81.83 46.208,82.045 48.367,82.045 49.64,80.772 v1(50.546,80.772) ; STM32F3.63 R20.2@50.273,90.118 ; R20.2 C3.2 v1(51.931,91.656) 56.223,91.656 ST_LINK/V2.14 ; C19.1 v1(51.473,22.733) ; ST_LINK/V2.8 ST_LINK/V2.8@56.57,84.074 ; v1(57.023,46.482) 57.035,46.494 60.603,46.494 T1.15 ; v1(58.42,42.164) 58.695,42.164 59.154,41.705 T1.3
  Top Layer w0.4: 7.07,19.517 TPS.3 ; 7.72,18.867 TPS.4 ; 8.37,18.217 TPS.5 ; v1(12.927,14.971) TPS.8@12.927,16.242 ; TPS.11 C12.1@22.86,17.567 ; R37.1@31.344,33.82 v1(31.344,35.857)
  Top Layer w0.5: v1(29.807,21.302) C20.1 ; v1(54.991,3.048) 56.254,4.311 MicroUSB.5
  Top Layer w0.6: C13.2 2.771,23.816 v1(5.77,20.817) 7.07,19.517 7.72,18.867 8.37,18.217 ; C15.2 18.874,24.18 18.289,24.765 v1(18.289,26.035) 18.289,28.575 19.559,29.845 v1(26.035,29.845) ; C18.1 51.103,19.569 51.473,19.939 C19.1 LM2.1@53.767,21.023 ; v1@48.006,10.286 48.661,10.941 R7.2 ; v1(61.214,16.236) C17.2
  other v1: 4.445,4.461 28.89,12.114 28.89,15.748 1.397,69.85 17.896,77.978 26.798,100.452 34.76,106.68
I2C_SCL: DS7.2 R30.1 STM32F3.61 | length 57.9
  Top Layer w0.254: DS7.2 7.017,101.904 8.083,101.904 8.255,102.076 8.255,103.445 8.404,103.594 R30.1 11.138,103.594 v2(12.065,104.521) ; v2(44.45,89.789) 45.121,89.118 STM32F3.61
  Bottom Layer w0.254: v2(12.065,104.521) 10.922,103.378 10.922,100.33 13.208,98.044 43.173,98.044 44.45,96.767 v2(44.45,89.789)
I2C_SDA: DS7.1 R29.1 STM32F3.62 | length 50.9
  Top Layer w0.254: DS7.1 7.027,101.277 8.098,101.277 R29.1@9.221,102.4 ; R29.1 R29.1@9.221,102.4 ; v2(12.192,102.362) 12.154,102.4 R29.1@9.221,102.4 ; v2(45.847,90.17) 46.399,89.618 STM32F3.62
  Bottom Layer w0.254: v2(12.192,102.362) 15.875,98.679 43.561,98.679 45.847,96.393 v2(45.847,90.17)
IREF_ADC: AD8.8 R31.2 STM32F3.14 | length 40
  Top Layer w0.254: R31.2 20,74.511 21.438,75.949 22.931,75.949 22.984,75.896 22.984,74.558 24.266,73.276 29.619,73.276 31.753,75.41 v2(32.639,75.41) ; v2(37.973,93.98) 39.589,93.98 39.993,93.576 STM32F3.14
  Bottom Layer w0.254: v2(32.639,75.41) 32.639,78.359 37.973,83.693 v2(37.973,93.98)
NetAD8_6: AD8.6 R34.2 | length 3.4
  Top Layer w0.254: R34.2 21.679,79.244 20.987,78.552 20.987,77.93 21.532,77.385 21.61,77.385 21.708,77.287 AD8.6 AD8.6@22.398,77.325
NetAD8_7: AD8.7 R31.1 R32.2 | length 4.4
  Top Layer w0.254: R32.2 19.939,76.122 20.01,76.122 20.526,76.637 AD8.7
NetC16_1: C16.1 LM1.5 | length 2.1
  Top Layer w0.254: LM1.5 27.382,24.13 C16.1
NetC16_2: C16.2 LM1.6 | length 2.9
  Top Layer w0.254: LM1.6 25.33,25.721 25.589,25.98 C16.2
NetC23_1: C23.1 STM32F3.5 X1.1 | length 29.2
  Top Layer w0.254: C23.1 35.741,104.975 X1.1 36.63,100.584 41.021,100.584 43.561,98.044 49.657,98.044 50.038,97.663 50.038,94.704 48.933,93.599 44.699,93.599 44.493,93.393 STM32F3.5
NetC24_1: C24.1 R19.1 X1.2 | length 23.6
  Top Layer w0.254: C24.1 30.861,104.864 X1.2 32.512,99.822 40.565,99.822 43.552,96.835 R19.1
NetCHG_C: CHG.C R1.1 | length 1.5
  Top Layer w0.254: CHG.C R1.1
NetCONNECT_A: CONNECT.A RN41.19 | length 4.2
  Top Layer w0.254: RN41.19 16.338,96.035 16.338,96.495 16.868,97.024 18.55,97.024 CONNECT.A
NetCONNECT_C: CONNECT.C R18.2 | length 4.1
  Top Layer w0.254: R18.2@18.669,100.038 R18.2 19.814,100.203 20.701,99.316 CONNECT.C
NetD7_A: D7.A R21.1 | length 1.7
  Top Layer w0.254: R21.1 40.436,76.614 40.943,76.107 D7.A
NetD8_A: D8.A R22.1 | length 1.6
  Top Layer w0.254: D8.A 43.472,76.351 44.3,76.351 R22.1
NetFULL_A: FULL.A R2.1 | length 1.6
  Top Layer w0.254: FULL.A R2.1
NetL1_2: L1.2 TPS.1 TPS.2 | length 11.2
  Top Layer w0.254: L1.2 6.465,25.582 11.23,20.817 ; TPS.2 11.88,20.167 11.23,20.817 ; TPS.1 11.23,20.817
NetLOW_A: LOW.A R6.1 | length 5
  Top Layer w0.254: R6.1 25.169,12.865 25.92,12.114 LOW.A
NetMCP_1: MCP.1 R1.2 R2.2 | length 13.3
  Top Layer w0.254: R2.2 34.671,12.865 ; MCP.1 34.995,12.541 34.671,12.865 ; R1.2 41.783,12.541 41.459,12.865 34.671,12.865
NetMCP_5: MCP.5 R3.1 | length 2.5
  Top Layer w0.254: MCP.5 39.855,11.491 R3.1
NetPWR_C: PWR.C R7.1 | length 2
  Top Layer w0.6: R7.1 PWR.C
NetQ1_1: Q1.1 TPS.10 | length 7.8
  Top Layer w0.254: Q1.1 20.304,14.843 20.844,15.383 20.844,16.582 20.509,16.917 TPS.10
NetQ1_3: Q1.3 R6.2 | length 6.6
  Top Layer w0.254: Q1.3 22.038,12.843 R6.2
NetR4_1: R4.1 R5.1 TPS.7 | length 7.7
  Top Layer w0.254: R5.1 R4.1 9.182,15.748 10.351,16.917 TPS.7
NetR14_2: R14.2 R15.1 TLC1.13 | length 7.2
  Top Layer w0.254: R15.1 R14.2 32.165,25.721 32.479,26.035 TLC1.13
NetR16_2: R16.2 STATE.C | length 2.6
  Top Layer w0.254: STATE.C 15.405,97.789 R16.2
NetR17_2: R17.2 RN41.22 | length 2.7
  Top Layer w0.254: R17.2 12.045,97.848 12.045,96.527 12.422,96.15 RN41.22@12.422,95.756
NetR19_2: R19.2 STM32F3.6 | length 6.5
  Top Layer w0.254: STM32F3.6 43.993,93.535 44.565,94.107 47.717,94.107 48.845,95.235 R19.2
NetR20_1: R20.1 STM32F3.60 | length 1.9
  Top Layer w0.254: STM32F3.60 50.353,88.618 R20.1
NetR21_2: R21.2 STM32F3.39 | length 3.6
  Top Layer w0.254: R21.2 40.386,78.681 41.993,80.288 STM32F3.39
NetR22_2: R22.2 STM32F3.40 | length 4.3
  Top Layer w0.254: STM32F3.40 42.493,80.299 43.036,79.756 44.088,79.756 44.623,79.221 R22.2
NetR23_2: R23.2 ST_LINK/V2.11 | length 19.9
  Top Layer w0.254: R23.2 55.736,105.118 56.422,104.432 57.765,104.432 60.96,101.237 60.96,91.313 ST_LINK/V2.11
NetR24_2: R24.2 ST_LINK/V2.17 | length 13
  Top Layer w0.254: R24.2 53.878,105.197 55.443,103.632 57.492,103.632 60.325,100.799 60.325,98.298 ST_LINK/V2.17
NetR25_2: R25.2 ST_LINK/V2.19 | length 10.4
  Top Layer w0.254: R25.2 51.981,105.246 54.484,102.743 57.246,102.743 58.801,101.188 ST_LINK/V2.19
NetR27_2: R27.2 STM32F3.44 | length 5.2
  Top Layer w0.254: STM32F3.44 44.493,79.993 47.321,77.165 R27.2 R27.2@47.421,77.165
NetR28_2: R28.2 STM32F3.45 | length 6
  Top Layer w0.254: STM32F3.45 44.993,80.186 46.901,78.278 47.67,78.278 48.768,77.18 R28.2
NetR35_1: R35.1 R37.2 TLC2.2 | length 4.7
  Top Layer w0.254: TLC2.2 26.454,33.401 26.873,33.82 R35.1 R37.2
NetR36_1: R36.1 R38.2 TLC2.6 | length 4.4
  Top Layer w0.254: R38.2 R36.1 18.289,34.963 18.581,34.671 TLC2.6
NetRN41_21: RN41.21 STATE.A | length 2
  Top Layer w0.254: RN41.21@13.622,95.756 13.728,95.862 13.728,97.624 STATE.A
NRST: C8.1 RESET.3 ST_LINK/V2.15 STM32F3.7 | length 32.9
  Top Layer w0.254: C8.1 40.894,101.956 41.43,101.42 42.305,101.42 RESET.3 44.919,98.806 v2(51.054,98.806) 54.293,95.567 57.468,95.567 ST_LINK/V2.15 ; STM32F3.7 43.493,93.677 44.939,95.123 v2(47.296,95.123)
  Bottom Layer w0.254: v2(47.296,95.123) 47.333,95.123 51.016,98.806 v2(51.054,98.806)
SPI_MISO: "Probe Points.7" STM32F3.35 T1.41 | length 39.6
  Top Layer w0.254: STM32F3.35 39.993,80.263 39.329,79.6 37.944,79.6 37.338,78.994 37.338,74.444 39.773,72.009 40.005,72.009 41.202,70.812 45.042,70.812 45.877,69.977 50.038,69.977 54.356,65.659 54.356,62.539 56.79,60.105 T1.41
SPI_MOSI: "Probe Points.8" STM32F3.36 T1.37 | length 46.7
  Top Layer w0.254: STM32F3.36 40.493,80.121 38.462,78.09 38.462,75.247 41.461,72.247 42.307,72.247 42.545,72.009 44.05,73.514 53.613,73.514 56.388,70.739 61.214,70.739 62.161,69.792 62.161,58.654 62.012,58.505 T1.37
SPI_SCK: "Probe Points.6" STM32F3.34 T1.29 | length 55.5
  Top Layer w0.254: STM32F3.34 39.493,80.406 39.141,80.054 36.524,80.054 36.195,79.725 36.195,73.279 37.465,72.009 39.497,69.977 45.003,69.977 47.875,67.105 47.875,52.524 50.361,50.038 53.323,50.038 58.59,55.305 T1.29
SPI_SS: "Probe Points.5" STM32F3.33 T1.33 | length 46
  Top Layer w0.254: v2(36.322,70.358) 34.925,71.755 34.925,72.009 35.514,72.598 35.514,79.93 36.702,81.118 STM32F3.33 ; v2(48.26,68.326) 50.8,68.326 53.848,65.278 53.848,62.235 59.178,56.905 T1.33
  Bottom Layer w0.254: v2(36.322,70.358) 46.228,70.358 v2(48.26,68.326)
SWCLK: ST_LINK/V2.9 STM32F3.49 | length 12.4
  Top Layer w0.254: STM32F3.49 49.303,83.118 50.125,82.296 51.113,82.296 54.098,85.281 57.468,85.281 ST_LINK/V2.9
SWDIO: ST_LINK/V2.7 STM32F3.46 | length 15.6
  Top Layer w0.254: STM32F3.46 45.516,81.141 45.516,81.995 46.02,82.499 49.28,82.499 49.937,81.842 51.377,81.842 52.276,82.741 57.468,82.741 ST_LINK/V2.7
TTN_CLK: "Probe Points.4" STM32F3.37 T1.25 | length 66.6
  Top Layer w0.254: 32.385,72.009 32.385,70.612 34.036,68.961 44.5,68.961 46.99,66.471 46.99,52.07 49.657,49.403 55.148,49.403 59.277,53.532 60.442,53.532 T1.25 ; v2(40.259,83.114) 40.993,82.38 STM32F3.37
  Bottom Layer w0.254: 32.385,72.009 32.385,73.152 34.33,75.097 34.33,79.408 38.036,83.114 v2(40.259,83.114)
TTN_PWM: "Probe Points.3" STM32F3.59 T1.21 | length 82.5
  Top Layer w0.254: STM32F3.59 39.921,88.118 39.141,87.338 39.141,83.195 37.518,81.572 34.925,81.572 33.68,80.327 33.68,74.953 33.01,74.283 32.119,74.283 29.845,72.009 29.845,69.977 31.75,68.072 44.069,68.072 45.819,66.322 45.819,51.717 48.895,48.641 55.906,48.641 59.234,51.969 60.479,51.969 T1.21
TTN_ready: "Probe Points.2" STM32F3.41 T1.17 | length 104.1
  Top Layer w0.254: 27.305,72.009 27.305,70.104 30.353,67.056 43.566,67.056 44.831,65.791 44.831,51.435 48.387,47.879 57.289,47.879 59.915,50.505 T1.17 v2(60.615,49.403) ; STM32F3.41 v2(42.993,83.212)
  Bottom Layer w0.254: v2(42.993,83.212) 46.201,83.212 55.753,73.66 60.325,73.66 62.161,71.824 62.161,50.949 v2(60.615,49.403)
UART_RX: RN41.14 STM32F3.52 UART1.2 | length 68.4
  Top Layer w0.254: v2(21.082,106.553) 21.082,104.394 UART1.2 21.209,100.452 22.069,99.591 RN41.14 ; STM32F3.52 v2(51.804,84.618)
  Bottom Layer w0.254: v2(21.082,106.553) 22.098,105.537 41.483,105.537 42.753,106.807 49.517,106.807 53.467,102.857 53.467,87.217 51.884,85.634 51.884,84.698 v2(51.804,84.618)
UART_TX: RN41.13 STM32F3.51 UART1.1 | length 68.7
  Top Layer w0.254: RN41.13 23.263,99.552 23.749,100.038 UART1.1 v2(23.749,106.553) ; STM32F3.51 48.502,84.109 49.749,84.109 v2(50.546,83.312)
  Bottom Layer w0.254: v2(23.749,106.553) 24.892,107.696 50.038,107.696 54.356,103.378 54.356,85.733 51.935,83.312 v2(50.546,83.312)
USART_RX: STM32F3.17 UART.5 | length 8.1
  Top Layer w0.254: UART.5 36.143,92.075 36.993,91.225 STM32F3.17 36.634,90.618 STM32F3.17@36.611,90.641
USART_TX: STM32F3.16 UART.6 | length 9.6
  Top Layer w0.254: UART.6 32.223,92.618 STM32F3.16
USB_DM: MicroUSB.2 R27.1 | length 83.9
  Top Layer w0.254: v2(46.333,74.525) 46.333,74.577 47.321,75.565 R27.1 ; v2(53.948,5.611) 54.598,6.261 MicroUSB.2
  Bottom Layer w0.254: v2(46.333,74.525) 47.437,74.525 49.53,72.431 49.53,67.437 49.403,67.31 49.403,14.576 ; 49.403,17.437 49.403,14.576 ; v2(53.948,5.611) 50.8,5.611 49.403,7.008 49.403,14.576
USB_DP: MicroUSB.3 R26.1 R28.1 | length 82.5
  Top Layer w0.254: R28.1 50.038,74.295 v2(51.181,74.295) ; v2(54.826,8.36) R26.1 ; v2(55.245,4.961) 55.895,5.611 MicroUSB.3
  Bottom Layer w0.254: v2(51.181,74.295) 50.165,73.279 50.165,9.63 51.435,8.36 v2(54.826,8.36) 55.245,7.941 v2(55.245,4.961)
VBAT: C11.2 L1.1 Q1.2 R4.2 SW-PWR.3 TPS.6 TPS.9 | length 34.8
  Top Layer w0.4: TPS.6 12.927,17.542 10.231,17.542 9.326,16.637 L1.1@5.77,16.637 ; SW-PWR.3 12.953,13.252 Q1.2 15.968,16.267 TPS.9 ; L1.1@5.77,16.637 L1.1 L1.1@5.77,16.637
  Top Layer w0.6: C11.2 L1.1 ; C11.2@5.726,14.097 R4.2
  Top Layer w1: C11.2 C11.2@5.726,14.097
  Bottom Layer w0.8: v1(5.715,16.637) 5.715,13.825 9.888,9.652 SW-PWR.3
Vcharge: R12.2 R13.1 TLC1.5 | length 4.7
  Top Layer w0.254: TLC1.5 R13.1 R12.2
Vcharge_buf: T1.7 TLC1.6 TLC1.7 | length 27.3
  Top Layer w0.254: TLC1.6 TLC1.7 41.459,32.405 v2(41.459,34.475) ; v2(45.212,38.608) 53.209,38.608 57.906,43.305 T1.7
  Bottom Layer w0.254: v2(41.459,34.475) 41.459,36.433 42.291,37.265 43.234,37.265 44.577,38.608 v2(45.212,38.608)
Vdac: R10.2 R11.1 TLC1.3 | length 4.7
  Top Layer w0.254: TLC1.3 R11.1 R10.2
Vdac_buf: T1.13 TLC1.1 TLC1.2 | length 40.3
  Top Layer w0.254: TLC1.2 TLC1.1 41.459,24.745 v2(41.459,22.733) ; v2(46.99,40.672) 47.126,40.672 47.61,40.188 53.192,40.188 58.709,45.705 T1.13
  Bottom Layer w0.254: v2(41.459,22.733) 42.555,22.733 43.188,23.366 43.188,34.475 46.99,38.277 v2(46.99,40.672)
VDAC_electrode: STM32F3.20 TLC2.3 | length 92.7
  Top Layer w0.254: TLC2.3 27.392,34.671 27.684,34.963 v2(27.684,35.857) ; v2(33.421,87.252) 34.273,87.252 36.139,89.118 STM32F3.20
  Bottom Layer w0.254: v2(27.684,35.857) 27.684,38.098 28.331,38.745 42.555,38.745 43.815,40.005 43.815,65.405 42.672,66.548 29.845,66.548 26.174,70.219 26.174,79.902 29.596,83.324 30.694,83.324 33.421,86.051 v2(33.421,87.252)
VDAC_electrode_amp: R35.2 TLC1.12 TLC2.1 | length 14.1
  Top Layer w0.254: TLC2.1 27.851,32.131 R35.2 30.006,32.22 v2(31.111,31.115) ; v2(33.655,27.305) TLC1.12
  Bottom Layer w0.254: v2(31.111,31.115) 31.111,29.849 v2(33.655,27.305)
VDAC_peltier: STM32F3.21 TLC2.5 | length 80.5
  Top Layer w0.254: TLC2.5 19.803,35.97 19.921,36.088 v2(19.921,37.084) ; v2(35.189,85.925) 35.189,87.526 36.258,88.595 36.97,88.595 STM32F3.21
  Bottom Layer w0.254: v2(19.921,37.084) 16.256,40.749 16.256,87.459 19.463,90.666 32.651,90.666 35.189,88.128 v2(35.189,85.925)
VDAC_peltier_amp: R36.2 TCA1.9 TLC2.7 | length 43.2
  Top Layer w0.254: TCA1.9 13.326,34.299 14.262,33.363 R36.2 17.183,33.401 TLC2.7
Velectrode_buf: AD8.2 R14.1 R33.2 TLC1.14 | length 88.9
  Top Layer w0.254: AD8.2 27.873,76.637 28.152,76.358 28.76,76.358 R33.2 29.133,76.035 30.441,77.343 v2(30.669,77.343) ; TLC1.14@35.412,24.659 35.518,24.765 TLC1.14 36.539,23.659 v2(37.465,22.733)
  Top Layer w0.5: R14.1 R14.1@33.871,24.765
  Top Layer w0.6: R14.1@33.871,24.765 TLC1.14@35.518,24.765
  Bottom Layer w0.254: v2(30.669,77.343) 30.669,74.992 28.436,72.759 28.436,69.018 30.152,67.302 43.144,67.302 44.577,65.869 44.577,40.07 42.734,38.227 36.068,38.227 35.052,37.211 35.052,33.782 37.465,31.369 v2(37.465,22.733)
VLiPo: C10.2 JSTPH.1 MCP.3 SW-PWR.2 | length 32.3
  Top Layer w0.8: JSTPH.1 14.462,6.461 SW-PWR.2 20.844,6.461 34.494,6.461 34.963,6.93 C10.2 34.963,9.559 MCP.3
Vpeltier_buf: Peltier.1 TCA1.10 TCA1.16 | length 14.6
  Top Layer w0.5: TCA1.16 12.806,79.502 11.811,78.507 11.811,72.877 12.806,71.882 TCA1.10 18.288,71.882 Peltier.1
VREF_electrode: "Probe Points.10" AD8.3 R33.1 T1.51 | length 61.5
  Top Layer w0.254: AD8.3 26.611,77.312 28.76,77.312 R33.1 29.133,77.635 29.762,78.264 29.762,78.53 v2(30.48,79.248) ; 47.625,72.009 v2(52.07,72.009) 53.594,72.009 57.785,67.818 57.785,65.416 59.096,64.105 T1.51
  Bottom Layer w0.254: v2(30.48,79.248) 31.623,78.105 31.623,74.549 31.115,74.041 31.115,70.358 32.004,69.469 32.766,69.469 33.794,70.497 33.794,73.164 37.211,76.581 50.419,76.581 52.07,74.93 v2(52.07,72.009)
Vtemp: R8.2 R9.1 TLC1.10 | length 7.3
  Top Layer w0.254: R8.2@33.655,34.475 R9.1 34.482,32.893 34.671,32.704 34.671,30.099 34.911,29.859 36.525,29.859 TLC1.10
Vtemp_buf: T1.9 TLC1.8 TLC1.9 | length 33
  Top Layer w0.254: TLC1.9 TLC1.8 v2(36.539,34.475) ; v2(46.101,39.59) 53.391,39.59 57.906,44.105 T1.9
  Bottom Layer w0.254: v2(36.539,34.475) 36.539,37.174 37.084,37.719 42.868,37.719 44.74,39.59 v2(46.101,39.59)
pads on no net: DS7.3 JSTPH.MP1 JSTPH.MP2 MicroUSB.4 MicroUSB.6 MicroUSB.7 MicroUSB.8 MicroUSB.9 MicroUSB.10 MicroUSB.11 RESET.2 RESET.4 RN41.2 RN41.3 RN41.4 RN41.5 RN41.6 RN41.7 RN41.8 RN41.9 RN41.10 RN41.15 RN41.16 RN41.17 RN41.18 RN41.20 RN41.23 RN41.24 RN41.30 RN41.31 RN41.32 RN41.33 RN41.34 RN41.35 STM32F3.2 STM32F3.3 STM32F3.4 STM32F3.8 STM32F3.9 STM32F3.10 STM32F3.11 STM32F3.15 STM32F3.22 STM32F3.23 STM32F3.24 STM32F3.25 STM32F3.26 STM32F3.27 STM32F3.28 STM32F3.29 STM32F3.30 STM32F3.38 STM32F3.42 STM32F3.43 STM32F3.50 STM32F3.53 STM32F3.54 STM32F3.55 STM32F3.56 STM32F3.57 STM32F3.58 SW-PWR.1 T1.2 T1.4 T1.5 T1.6 T1.8 T1.10 T1.11 T1.12 T1.14 T1.16 T1.18 T1.19 T1.20 T1.22 T1.23 T1.24 T1.26 T1.27 T1.28 T1.30 T1.31 T1.32 T1.34 T1.35 T1.36 T1.38 T1.39 T1.40 T1.42 T1.43 T1.44 T1.46 T1.47 T1.48 T1.50 T1.52 T1.MH1 T1.MH2 T1.MP1C T1.MP2C T2.MH3 T2.MH4 T2.MP1L T2.MP2L T2.MP3L T2.MP4L TCA1.2 TCA1.3 TCA1.6 TCA1.11 TCA1.14 TCA1.15 TPS.12 TPS.PowerPAD
copper on no net: | length 0
  Top Layer w0.254: 48.493,87.618 48.516,87.595

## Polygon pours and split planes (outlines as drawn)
GND on Bottom Layer "GND_L02_P106" (solid, pour order 106): 0.127,0.127 0.127,108.458 62.484,108.458 62.484,0.127
no net on Bottom Layer "NONET_L02_P105" (solid, pour order 105): 0.127,0.127
no net on Bottom Layer "Bottom Layer-No Net" (solid, pour order 66): 18.923,81.534 28.829,81.534
no net on Bottom Layer "Bottom Layer-No Net 1" (solid, pour order 54): 18.923,81.534
no net on Bottom Layer "Bottom Layer-No Net 2" (solid, pour order 0): -30.861,61.214
+5VDD on Top Layer "+5VDD_L01_P097" (solid, pour order 97): 19.052,23.18 26.035,23.18 26.035,18.867 19.052,18.867
no net on Top Layer "NONET_L01_P103" (solid, pour order 103): 16.637,37.719
GND on Top Layer "GND_L01_P101" (solid, pour order 101): 9.906,3.937 3.175,3.937 3.175,6.985 4.953,6.985 4.953,12.891 8.149,12.891 8.149,8.382 5.715,8.382 5.715,5.08 9.906,5.08
GND on Top Layer "GND_L01_P100" (solid, pour order 100): 22.06,18.217 22.06,14.097 26.873,14.097 26.873,7.366 33.871,7.366 33.871,8.382 30.099,8.382 30.099,16.582 26.873,16.582 26.873,18.217
no net on Top Layer "NONET_L01_P096" (solid, pour order 96): 28.448,23.18
no net on Top Layer "NONET_L01_P095" (solid, pour order 95): 19.052,19.517
no net on Top Layer "NONET_L01_P094" (solid, pour order 94): 17.653,18.867
GND on Top Layer "Top Layer-GND 3" (solid, remove dead copper, pour order 14): 9.398,95.758 9.398,82.446 28.255,82.446 28.321,82.512 28.321,95.756
GND on Top Layer "Top Layer-GND 1" (solid, remove dead copper, pour order 81): 39.243,108.585 39.243,104.013 62.738,104.013 62.738,108.585
GND on Top Layer "Top Layer-GND 2" (solid, remove dead copper, pour order 77): 27.88,108.071 39.493,108.071 39.493,98.806 38.735,98.806 27.88,98.806
GND on Top Layer "Top Layer-GND" (solid, remove dead copper, pour order 89): 19.812,73.533 19.812,70.739 19.885,70.812 23.136,70.812 23.114,70.834 23.114,78.613 25.654,78.613 25.654,77.635 27.981,77.635 28.702,78.356 28.702,80.121 22.902,80.121 21.743,81.28 16.312,81.28 12.319,77.287 12.319,73.533
GND on Top Layer "Top Layer-GND 4" (solid, remove dead copper, pour order 38): 0.635,77.597 4.318,77.597 4.318,69.215 0.635,69.215
no net on Top Layer "Top Layer-No Net" (solid, pour order 40): 13.081,78.74
no net on Top Layer "Top Layer-No Net 1" (solid, pour order 30): 11.303,35.179
no net on Top Layer "Top Layer-No Net 2" (solid, pour order 16): 62.738,17.018
no net on Top Layer "Top Layer-No Net 3" (solid, pour order 4): 0,108.585
no net on Top Layer "Top Layer-No Net 4" (solid, pour order 2): -0.127,108.839

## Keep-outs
Keep-Out Layer:
  lines w0.5: 19.188,64.705 19.188,40.672 43.188,40.672 43.188,64.705 19.377,64.705 ; 0,0 62.738,0 62.738,108.585 0,108.585 0,0

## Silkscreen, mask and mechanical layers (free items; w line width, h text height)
Top Overlay:
  drawing of 6186 lines, arcs and shapes, not listed
  text "Tx" at 23.368,101.994 h0.6
  text "Rx" at 20.701,101.981 h0.6
  text "CTS" at 27.178,94.234 h0.6
  text "TX" at 27.686,91.694 h0.6
  text "RX" at 27.686,89.281 h0.6
  text "5V" at 27.686,86.741 h0.6
  text "RTS" at 27.178,84.201 h0.6
  text "GND" at 27.051,81.788 h0.6
  text "SS" at 35.179,69.215 h0.6 r90
  text "GND" at 25.146,68.707 h0.6 r90
  text "RDY" at 27.559,68.704 h0.6 r90
  text "PWM" at 30.226,68.707 h0.6 r90
  text "TCK" at 32.766,68.707 h0.6 r90
  text "SCK" at 37.846,68.707 h0.6 r90
  text "MOSI" at 42.926,68.326 h0.6 r90
  text "MISO" at 40.386,68.199 h0.6 r90
  text "3.3V" at 45.466,68.199 h0.6 r90
  text "VREF" at 47.371,68.072 h0.6 r90
  text "CHARGE" at 19.431,5.984 h1
  text "POWER" at 10.541,5.969 h1 r0.18
  text "Jan 2020" at 16.381,3.937 h0.8
  text "Lacewing PXE v3.1" at 16.381,2.413 h0.8
  text "For clinical trials" at 16.418,0.833 h0.8

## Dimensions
0,108.585 to 0,0 on Mechanical 1
0,0 to 62.738,0 on Mechanical 1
